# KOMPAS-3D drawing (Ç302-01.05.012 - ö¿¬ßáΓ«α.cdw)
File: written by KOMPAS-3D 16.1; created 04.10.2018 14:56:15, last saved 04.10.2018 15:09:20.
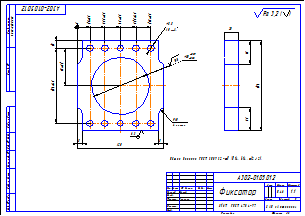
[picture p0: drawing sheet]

Sheet 1: A3, landscape

Title block, sheet 1: name: Фиксатор; designation: А302-01.05.012; mass: 0,46; scale: 1:1; sheets: 1; organisation: ЗАО «Астерион»; sheet format: A3; stored path: \\192.168.87.28\Konstructor_doc\Мембранные насосы\Мембранный электропривод\А302-00.00.000 - ASTRA-302 (МЭ200)\3Д ПВХ\А302-01.05.012 - Фиксатор.cdw; drawn by: Милов; technical control: Лучихин

Views: Вид 1, Спереди, Проекционный вид 2
Referenced files in \\192.168.87.28\Konstructor_doc\Мембранные насосы\Мембранный электропривод\А302-00.00.000 - ASTRA-302 (МЭ200)\3Д ПВХ\Отработка\: Фиксатор.m3d
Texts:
  Д16Т  ГОСТ 4784-97
  Общие допуски ГОСТ 30893.2-mK (H14, h14,  t2/2).
  Ra 3,2
  Ra 3,2 ( )
Dimensions and other numbers on the sheet: 120; 18±0,2; 38,5±0,2; 60±0,2; 81,5±0,2; 102±0,2; 80; 0,8; 8,8; 10 отв.; 8; 10; 4 места; 104±0,2; 52±0,1; 6,3; 20; 32; 124; 1:1; 1; 0,46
